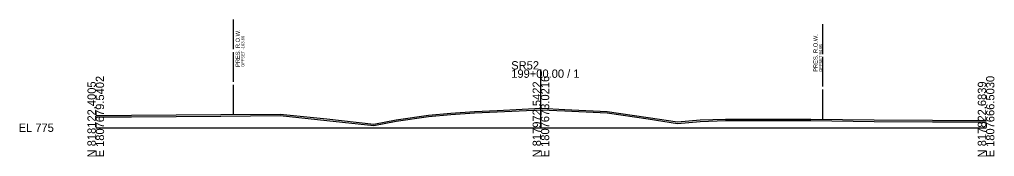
# Model space of a CAD drawing. Extents: x -50 to 1838305, y -27 to 820775.
# Drawn here: x -25.7 to 302.8, y -9.7 to 36.5 of the extents above; entities that cross this region are included whole.
import ezdxf

# ---------------------------------------------------------------- set-up
doc = ezdxf.new("R2010")
doc.units = 0
for name, color, linetype in [('DESIGN - SHEET - Light Grid', 7, 'Continuous'), ('SURVEY - GROUND - Bottom of Topsoil Layer', 7, 'Continuous'), ('SURVEY - GROUND - Top of Ground', 7, 'Continuous'), ('SURVEY - PROPERTY - ROW Lines', 7, 'Continuous'), ('SURVEY - PROPERTY - ROW Lines Text', 7, 'Continuous')]:
    doc.layers.add(name, color=color, linetype=linetype)

msp = doc.modelspace()

# ---------------------------------------------------------------- linework, layer by layer
at = {"layer": 'DESIGN - SHEET - Light Grid'}
for p, q in [((150, 0), (150, 19.62)), ((0, 0), (150, 0)), ((150, 0), (300, 0))]:
    msp.add_line(p, q, dxfattribs=at)
at = {"layer": 'SURVEY - GROUND - Bottom of Topsoil Layer'}
for p, q in [((0, 3.66), (12.06, 3.72)), ((12.06, 3.72), (42.1, 3.93)), ((42.1, 3.93), (62.11, 4.1)), ((62.11, 4.1), (77.89, 2.47)), ((101.26, 2.16), (112.16, 3.78)), ((112.16, 3.78), (119.64, 4.46)), ((119.64, 4.46), (127.65, 4.98)), ((127.65, 4.98), (135.3, 5.33)), ((135.3, 5.33), (150.07, 6.04)), ((150.07, 6.04), (158.11, 5.66)), ((158.11, 5.66), (172.34, 4.97)), ((172.34, 4.97), (186.19, 2.97)), ((77.89, 2.47), (93.7, 0.75)), ((93.7, 0.75), (101.26, 2.16)), ((186.19, 2.97), (196.01, 1.46)), ((196.01, 1.46), (203.61, 2.14)), ((203.61, 2.14), (212.25, 2.44)), ((212.25, 2.44), (240.91, 2.39)), ((240.91, 2.39), (262.3, 2.15)), ((262.3, 2.15), (281.91, 2.01)), ((281.91, 2.01), (300, 1.98))]:
    msp.add_line(p, q, dxfattribs=at)
at = {"layer": 'SURVEY - GROUND - Top of Ground'}
msp.add_lwpolyline([(0, 4.16), (12.06, 4.22), (42.1, 4.43), (62.11, 4.6), (77.89, 2.97), (93.7, 1.25), (101.26, 2.66), (112.16, 4.28), (119.64, 4.96), (127.65, 5.48), (135.3, 5.83), (150.07, 6.54), (158.11, 6.16), (172.34, 5.47), (186.19, 3.47), (196.01, 1.96), (203.61, 2.64), (212.25, 2.94), (240.91, 2.89), (262.3, 2.65), (281.91, 2.51), (300, 2.48)], dxfattribs=at)
at = {"layer": 'SURVEY - PROPERTY - ROW Lines'}
for p, q in [((46.4, 26.47), (46.4, 36.47)), ((244.98, 24.84), (244.98, 34.84)), ((46.4, 15.47), (46.4, 25.47)), ((244.98, 13.84), (244.98, 23.84)), ((46.4, 4.47), (46.4, 14.47)), ((244.98, 2.84), (244.98, 12.84))]:
    msp.add_line(p, q, dxfattribs=at)

# ---------------------------------------------------------------- texts
at = {"layer": 'DESIGN - SHEET - Light Grid'}
for s, p in [('SR52', (140, 19.62)), ('199+00.00 / 1', (140, 16.82)), ('EL 775', (-26, -1.4))]:
    msp.add_text(s, height=2.8, dxfattribs=at).set_placement(p)
for s, p in [('E 1807679.5402', (2.8, -10)), ('E 1807673.0216', (152.8, -10)), ('E 1807666.5030', (302.8, -10)), ('N 818122.4005', (0, -10)), ('N 817972.5422', (150, -10)), ('N 817822.6839', (300, -10))]:
    msp.add_text(s, height=2.8, rotation=90, dxfattribs=at).set_placement(p)
at = {"layer": 'SURVEY - PROPERTY - ROW Lines Text'}
for s, height, p in [('PRES. R.O.W.', 1.4, (48.55, 20.47)), ('OFFSET -103.60', 1, (50.05, 20.47)), ('PRES. R.O.W.', 1.4, (243.23, 18.84)), ('OFFSET 94.98', 1, (244.73, 18.84))]:
    msp.add_text(s, height=height, rotation=90, dxfattribs=at).set_placement(p)

doc.saveas('drawing.dxf')
